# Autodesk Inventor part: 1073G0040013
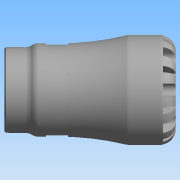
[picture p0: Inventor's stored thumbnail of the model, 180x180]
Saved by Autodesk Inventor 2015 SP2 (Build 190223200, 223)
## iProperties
Created: 2016-12
Part Number: 1073G0040013
Material: Generic
Description: PLASSON FEMALE INTEGRAL BRASS THREAD 40X1.1/4"G SERIES 1
Document SubType Name: Modeling
Designer: KIM
Density: 1 g/cm^3
Appearance: Default
Author: KIM
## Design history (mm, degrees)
derived "1073G.ipt"
feature "Solid1::1073G.ipt"
tag "TaggingFeature1"
body "Solid1"
other parameters: "d0" = 109, "d1" = 30.66, "d6" = 73, "d8" = 59.5, "d13" = 8, "d14" = 8, "d15" = 0, "d17" = 360 deg, "d19" = 8 deg, "d20" = 0.8, "d21" = 0.8, "d22" = 8 deg, "d24" = 0, "d26" = 360 deg, "d32" = 7, "d33" = 7, "d39" = 1.16856, "d42" = 38.952, "d43" = 54.6, "d46" = 3.33333, "d47" = 19, "d48" = 37.0044, "d50" = 5.61, "d51" = 0.7, "d54" = 14, "d55" = 8.8, "d57" = 15.68, "d58" = 0, "d68" = 360 deg, "d72" = 0.8, "d74" = 0, "d76" = 11.9, "H_" = 109, "l_" = 73, "G_" = 38.952, "l_2" = 19, "d9" = 10, "d49" = 17
